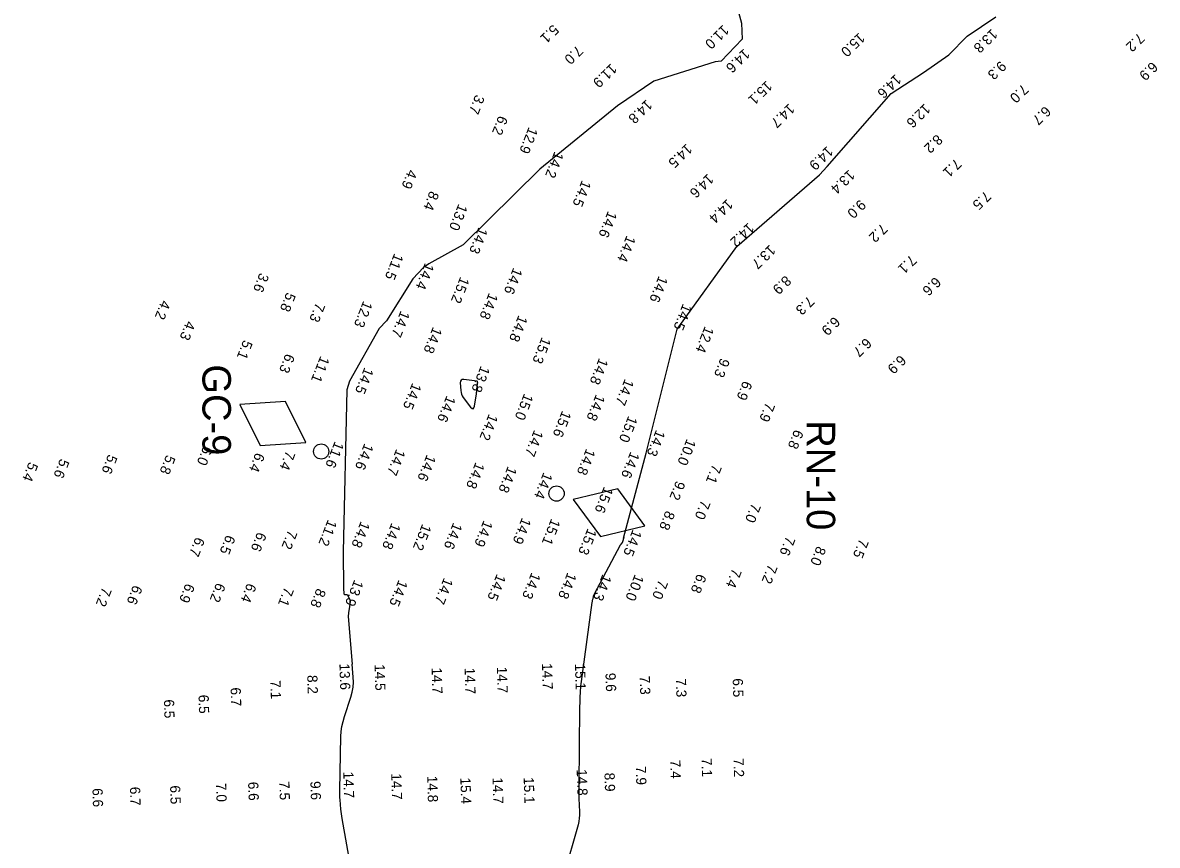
# Model space of a CAD drawing. Extents: x 824616 to 827440, y 158441 to 163197.
# Drawn here: x 825489 to 826046, y 162120 to 162524 of the extents above; entities that cross this region are included whole.
import ezdxf

# ---------------------------------------------------------------- set-up
doc = ezdxf.new("R2010")
doc.units = 0
for name, color, linetype in [('V-CHAN-CONT-EL14', 7, 'Continuous'), ('V-CHAN-NAID', 7, 'Continuous'), ('V-TOPO-SOUN', 7, 'Continuous'), ('V-TOPO-SOUN-EXSS', 7, 'Continuous')]:
    doc.layers.add(name, color=color, linetype=linetype)

msp = doc.modelspace()

# ---------------------------------------------------------------- linework, layer by layer
at = {"layer": 'V-CHAN-CONT-EL14'}
for points in [[(825836.26, 162545.19), (825842.02, 162524.1), (825842.23, 162516.14), (825831.92, 162505.48), (825829, 162505.03), (825798.85, 162495.55), (825781.07, 162483.52), (825742.86, 162452.3), (825705.06, 162415.19), (825688.22, 162405.75), (825685.57, 162403.9), (825680.43, 162398.39), (825667.45, 162377.71), (825663.83, 162374.01), (825649.2, 162348.08), (825647.92, 162343.78), (825646.05, 162264.2), (825646.35, 162246.34), (825646.45, 162243.64), (825646.76, 162243.32), (825647.92, 162243.21), (825648.38, 162242.74), (825649.42, 162240.64), (825649.55, 162240.2), (825649.6, 162239.72), (825649.23, 162237.31), (825648.71, 162234.16), (825648.61, 162232.51), (825650.53, 162209.06)], [(825783.98, 162270.98), (825795.1, 162312.69), (825810.36, 162373.61), (825839.65, 162414.36), (825880.3, 162449.56), (825884.08, 162453.7), (825915.47, 162489.58), (825931.41, 162499.83), (825943.85, 162508.57), (825952.94, 162517.67), (825967.03, 162527.15)], [(825784.1, 162271.46), (825783.61, 162269.62), (825783.55, 162269.42), (825783.47, 162269.23), (825783.38, 162269.04), (825783.27, 162268.86), (825782.8, 162268.17), (825782.69, 162267.99), (825782.58, 162267.81), (825782.47, 162267.63), (825782.37, 162267.45), (825769.51, 162243.44), (825769.35, 162243.11), (825769.21, 162242.78), (825769.1, 162242.44), (825769.01, 162242.09), (825768.68, 162240.67), (825768.61, 162240.31), (825768.54, 162239.95), (825768.48, 162239.59), (825768.42, 162239.23), (825763.13, 162200.49), (825762.99, 162199.41), (825762.88, 162198.33), (825762.79, 162197.25), (825762.72, 162196.17), (825762.5, 162191.83), (825762.45, 162190.74), (825762.41, 162189.66), (825762.39, 162188.57), (825762.37, 162187.49), (825761.95, 162149.56), (825761.95, 162147.92), (825761.96, 162146.29), (825762, 162144.65), (825762.06, 162143.02), (825762.34, 162136.48), (825762.35, 162134.85), (825762.23, 162133.24), (825761.97, 162131.65), (825761.59, 162130.07), (825754.57, 162105.52)], [(825652.57, 162094.38), (825645.63, 162133.12), (825645.44, 162134.27), (825645.27, 162135.42), (825645.14, 162136.57), (825645.03, 162137.73), (825644.65, 162142.37), (825644.56, 162143.53), (825644.51, 162144.69), (825644.49, 162145.85), (825644.5, 162147.02), (825645.06, 162173.36), (825645.2, 162175.87), (825645.53, 162178.35), (825646.05, 162180.79), (825646.74, 162183.21), (825649.91, 162192.79), (825650.58, 162195.21), (825650.99, 162197.65), (825651.16, 162200.12), (825651.07, 162202.62), (825650.53, 162209.06)]]:
    msp.add_lwpolyline(points, dxfattribs=at)
msp.add_lwpolyline([(825712.26, 162347.18), (825712.26, 162347.29), (825712.25, 162347.4), (825712.2, 162347.84), (825712.18, 162347.94), (825712.13, 162348.02), (825712.06, 162348.07), (825711.96, 162348.09), (825705.43, 162348.89), (825704.62, 162348.88), (825704.06, 162348.6), (825703.75, 162348.05), (825703.69, 162347.24), (825703.93, 162343.49), (825704.06, 162342.57), (825704.31, 162341.7), (825704.69, 162340.88), (825705.2, 162340.11), (825708.81, 162335.39), (825709.47, 162334.7), (825710, 162334.55), (825710.4, 162334.93), (825710.65, 162335.85), (825711.64, 162341.96), (825711.72, 162342.48), (825711.8, 162343), (825711.86, 162343.52), (825711.92, 162344.04), (825712.24, 162346.96), (825712.25, 162347.07)], close=True, dxfattribs=at)
at = {"layer": 'V-CHAN-NAID'}
for points in [[(825627.77, 162317.9), (825617.81, 162338.05), (825595.38, 162336.6), (825605.34, 162316.46)], [(825759.25, 162289.87), (825772.56, 162271.75), (825794.4, 162277.07), (825781.09, 162295.18)]]:
    msp.add_lwpolyline(points, close=True, dxfattribs=at)
for centre in [(825635.33, 162313.54), (825751.05, 162292.85)]:
    msp.add_circle(centre, 3.74, dxfattribs=at)

# ---------------------------------------------------------------- texts
for s, p in [('GC-9', (825576.94, 162356.36)), ('RN-10', (825874.03, 162328.89))]:
    msp.add_text(s, height=14, rotation=270, dxfattribs=at).set_placement(p)
at = {"layer": 'V-TOPO-SOUN'}
for s, rotation, p in [('5.1', 224.2, (825749.25, 162523.74)), ('11.0 ', 224.2, (825832.91, 162523.54)), ('15.0 ', 224.2, (825899.73, 162519.7)), ('13.8 ', 224.2, (825964.95, 162521.61)), ('7.2', 224.2, (826037.19, 162519.58)), ('7.0', 224.2, (825761.13, 162513.42)), ('14.6 ', 224.2, (825843.18, 162511.84)), ('11.9 ', 224.2, (825777.79, 162504.53)), ('9.3', 224.2, (825969.22, 162505.86)), ('6.9', 224.2, (826043.7, 162505.46)), ('15.1 ', 224.2, (825854.18, 162496.09)), ('14.6 ', 224.2, (825917.65, 162499.3)), ('3.7', 248.4, (825711.22, 162489.26)), ('7.0', 224.2, (825980.13, 162494.43)), ('14.8 ', 224.2, (825795.24, 162486.85)), ('14.7 ', 224.2, (825865.23, 162484.84)), ('12.6 ', 224.2, (825931.94, 162484.82)), ('6.2', 248.4, (825722.63, 162478.96)), ('6.7', 224.2, (825991.15, 162483.64)), ('12.9 ', 248.4, (825737.4, 162473.29)), ('8.2', 224.2, (825937.93, 162469.73)), ('14.2 ', 248.4, (825750.11, 162461.31)), ('14.5 ', 224.2, (825814.86, 162465.13)), ('14.9 ', 224.2, (825884.12, 162463.97)), ('7.1', 224.2, (825947.16, 162457.82)), ('4.9', 248.4, (825678.11, 162452.49)), ('14.6 ', 224.2, (825825.41, 162450.35)), ('13.4 ', 224.2, (825894.78, 162452.34)), ('14.5 ', 248.4, (825763.57, 162447.18)), ('8.4', 248.4, (825688.82, 162441.93)), ('7.5', 224.2, (825961.75, 162441.9)), ('13.0 ', 248.4, (825702.86, 162435.49)), ('14.4 ', 224.2, (825834.9, 162437.93)), ('9.0', 224.2, (825900.18, 162437.69)), ('14.6 ', 248.4, (825776.36, 162432.03)), ('14.3 ', 248.4, (825712.75, 162424.04)), ('14.2 ', 224.2, (825845.31, 162426.3)), ('7.2', 224.2, (825910.83, 162425.9)), ('14.4 ', 248.4, (825785.52, 162420.03)), ('11.5 ', 248.4, (825671.33, 162411.22)), ('13.7 ', 224.2, (825855.84, 162415.44)), ('14.4 ', 248.4, (825686.4, 162406.5)), ('7.1', 224.2, (825925.1, 162410.41)), ('3.6', 248.4, (825605.19, 162401.68)), ('14.6 ', 248.4, (825729.84, 162404.16)), ('14.6 ', 248.4, (825801.34, 162400.15)), ('8.9', 224.2, (825863.5, 162400.35)), ('15.2 ', 248.4, (825703.78, 162399.72)), ('6.6', 224.2, (825937.13, 162399.68)), ('5.8', 248.4, (825618.36, 162392.09)), ('14.8 ', 248.4, (825717.85, 162391.79)), ('7.3', 224.2, (825874.83, 162390.22)), ('4.2', 248.4, (825556.84, 162388.26)), ('7.3', 248.4, (825632.79, 162387)), ('12.3 ', 248.4, (825656.12, 162387.85)), ('14.5 ', 248.4, (825813.21, 162386.47)), ('4.3', 248.4, (825569.04, 162378.09)), ('14.7 ', 248.4, (825674.47, 162383.05)), ('14.8 ', 248.4, (825732.37, 162380.78)), ('6.9', 224.2, (825887.49, 162380.16)), ('14.8 ', 248.4, (825690.33, 162375.07)), ('12.4 ', 248.4, (825823.98, 162375.41)), ('5.1', 248.4, (825597.17, 162368.67)), ('15.3 ', 248.4, (825743.85, 162370.04)), ('6.7', 224.2, (825903.02, 162369.68)), ('6.3', 248.4, (825617.92, 162361.97)), ('6.9', 224.2, (825919.96, 162361.28)), ('11.1 ', 248.4, (825635.01, 162360.76)), ('13.8 ', 248.4, (825713.86, 162355.95)), ('14.8 ', 248.4, (825772.01, 162359.74)), ('9.3', 248.4, (825831.76, 162359.81)), ('14.5 ', 248.4, (825656.64, 162355.14)), ('14.5 ', 248.4, (825680.19, 162347.54)), ('14.7 ', 248.4, (825784.65, 162349.53)), ('6.9', 248.4, (825842.83, 162348.59)), ('14.6 ', 248.4, (825697.03, 162341.29)), ('15.0 ', 248.4, (825735.17, 162342.31)), ('14.8 ', 248.4, (825770.46, 162341.92)), ('15.6 ', 248.4, (825753.85, 162333.89)), ('7.9', 248.4, (825853.97, 162338)), ('14.2 ', 248.4, (825717.83, 162332.3)), ('15.0 ', 248.4, (825786.39, 162331.35)), ('14.7 ', 248.4, (825740.1, 162324.42)), ('14.3 ', 248.4, (825800.04, 162324.48)), ('6.8', 248.4, (825868.04, 162324.64)), ('6.0', 248.4, (825577.5, 162316.58)), ('11.6 ', 248.4, (825642.06, 162318.81)), ('14.6 ', 248.4, (825656.63, 162317.82)), ('10.0 ', 248.4, (825815.13, 162320.07)), ('5.6', 248.4, (825530.69, 162312.43)), ('5.8', 248.4, (825559.23, 162312.18)), ('6.4', 248.4, (825603.14, 162313.29)), ('7.4', 248.4, (825618.12, 162314.23)), ('14.7 ', 248.4, (825672.31, 162315.03)), ('14.6 ', 248.4, (825687.3, 162312.29)), ('14.8 ', 248.4, (825765.69, 162315.25)), ('14.6 ', 248.4, (825787.45, 162313.74)), ('5.4', 248.4, (825491.69, 162308.68)), ('5.6', 248.4, (825507.07, 162310.32)), ('14.8 ', 248.4, (825711.26, 162308.55)), ('14.8 ', 248.4, (825727.14, 162306.57)), ('7.1', 248.4, (825827.78, 162307.59)), ('14.4 ', 248.4, (825744.67, 162303.59)), ('9.2', 248.4, (825809.86, 162299.5)), ('7.0', 248.4, (825822.25, 162289.97)), ('8.8', 248.4, (825804.8, 162284.77)), ('7.0', 248.4, (825847.03, 162288.45)), ('11.2 ', 248.4, (825638.68, 162280.38)), ('14.8 ', 248.4, (825654.86, 162279.53)), ('14.8 ', 248.4, (825669.98, 162278.73)), ('15.2 ', 248.4, (825685.08, 162278.21)), ('14.6 ', 248.4, (825700.3, 162278.83)), ('14.9 ', 248.4, (825715.25, 162279.99)), ('14.9 ', 248.4, (825734.1, 162281.32)), ('15.1 ', 248.4, (825748.48, 162280.81)), ('6.5', 248.4, (825588.71, 162272.84)), ('6.6', 248.4, (825604.03, 162274.25)), ('7.2', 248.4, (825619.15, 162275.31)), ('15.3 ', 248.4, (825766.37, 162276.05)), ('14.5 ', 248.4, (825788.51, 162275.43)), ('6.7', 248.4, (825573.68, 162271.78)), ('7.6', 248.4, (825863.96, 162272.21)), ('8.0', 248.4, (825879.06, 162267.35)), ('7.5', 248.4, (825900.04, 162270.97)), ('7.4', 248.4, (825837.57, 162256.4)), ('7.2', 248.4, (825855.19, 162258.43)), ('13.9 ', 248.4, (825651.68, 162250.78)), ('14.5 ', 248.4, (825673.45, 162250.74)), ('14.7 ', 248.4, (825695.72, 162251.77)), ('14.5 ', 248.4, (825721.69, 162253.59)), ('14.3 ', 248.4, (825738.79, 162254.37)), ('14.8 ', 248.4, (825756.47, 162254.37)), ('14.3 ', 248.4, (825773.65, 162253.46)), ('10.0 ', 248.4, (825789.58, 162253.44)), ('7.0', 248.4, (825801.35, 162250.79)), ('6.8', 248.4, (825820.29, 162253.75)), ('7.2', 248.4, (825527.85, 162247.17)), ('6.6', 248.4, (825543.02, 162248.18)), ('6.9', 248.4, (825568.78, 162249.02)), ('6.2', 248.4, (825583.86, 162249.3)), ('6.4', 248.4, (825599.04, 162249.15)), ('7.1', 248.4, (825617.41, 162247.22)), ('8.8', 248.4, (825633.23, 162246.62)), ('13.6 ', 271.8, (825644.27, 162209.27)), ('14.5 ', 271.8, (825661.56, 162208.91)), ('14.7 ', 271.8, (825689.6, 162207.28)), ('14.7 ', 271.8, (825705.84, 162207.2)), ('14.7 ', 271.8, (825721.66, 162207.68)), ('14.7 ', 271.8, (825743.85, 162209.42)), ('15.1 ', 271.8, (825760.06, 162209.23)), ('9.6', 271.8, (825775.08, 162204.66)), ('7.1', 271.8, (825610.32, 162201)), ('8.2', 271.8, (825628.44, 162203.58)), ('7.3', 271.8, (825791.89, 162203.2)), ('7.3', 271.8, (825809.67, 162201.95)), ('6.5', 271.8, (825837.62, 162201.96)), ('6.5', 271.8, (825575, 162193.9)), ('6.7', 271.8, (825590.78, 162197.48)), ('6.5', 271.8, (825557.99, 162191.59)), ('7.4', 271.8, (825806.91, 162161.92)), ('7.1', 271.8, (825822.3, 162162.76)), ('7.2', 271.8, (825838.01, 162162.68)), ('14.7 ', 271.8, (825646.17, 162156.11)), ('14.7 ', 271.8, (825669.75, 162155.27)), ('14.8 ', 271.8, (825760.92, 162157.29)), ('8.9', 271.8, (825774.58, 162155.6)), ('7.9', 271.8, (825789.98, 162158.83)), ('6.7', 271.8, (825541.3, 162148.66)), ('6.5', 271.8, (825561.02, 162149.33)), ('7.0', 271.8, (825583.61, 162150.5)), ('6.6', 271.8, (825599.4, 162151.11)), ('7.5', 271.8, (825614.69, 162151.38)), ('9.6', 271.8, (825630, 162151.44)), ('14.8 ', 271.8, (825687.41, 162154.06)), ('15.4 ', 271.8, (825703.72, 162153.21)), ('14.7 ', 271.8, (825719.55, 162153.27)), ('15.1 ', 271.8, (825734.86, 162153.38)), ('6.6', 271.8, (825522.85, 162147.97))]:
    msp.add_text(s, height=5, rotation=rotation, dxfattribs=at).set_placement(p)
at = {"layer": 'V-TOPO-SOUN-EXSS'}
msp.add_text('15.6 ', height=5, rotation=248.4, dxfattribs=at).set_placement((825774.43, 162296.59))

doc.saveas('drawing.dxf')
